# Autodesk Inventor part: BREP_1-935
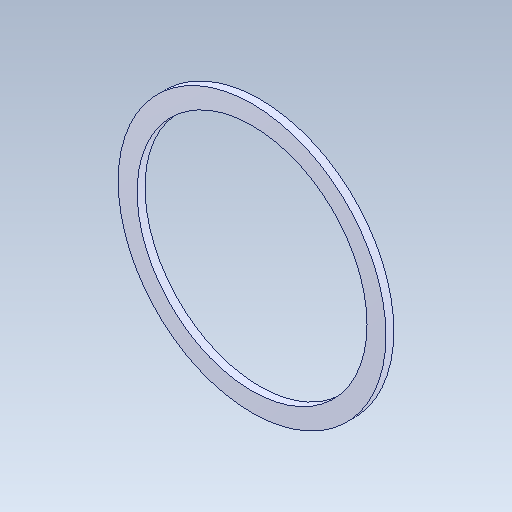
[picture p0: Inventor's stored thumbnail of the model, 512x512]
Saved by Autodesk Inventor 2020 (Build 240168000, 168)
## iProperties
Created: 2017-09
Part Number: BREP_1-935
Material: Générique
Document SubType Name: Modeling
Designer: bruno
Density: 1 g/cm^3
Appearance: Par défaut
Author: bruno
Sending System: SolidWorks 2016
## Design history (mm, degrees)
feature "Importée1"
node "Solide1"
